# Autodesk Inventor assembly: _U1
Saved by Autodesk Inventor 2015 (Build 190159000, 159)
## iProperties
Created: 2015-06
Part Number: _U1
Document SubType Name: Assembly
Designer: Franzi-CAD
Translation Standard: IGES 5.3
FileName: 1 Sistema de RefrigeraÃ§Ã£o Industrial - 3D v3
PreProcessor: AutoCAD 2015 - English
PostProcessor: Build: 160, Release: 2012 RTM - Date: Tue 03/01/2011
Sent Units: millimeter
Uncertainty: 0.01
Author: Franzi-CAD
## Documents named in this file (2)
- C:\Users\Renato\Desktop\Refrigeração\_U1.iam
- C:\Users\Renato\Desktop\Refrigeração\_U0.ipt
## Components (4 placed, 1 different names)
1. _U0:1
2. _U0:2
3. _U0:3
4. _U0:4
